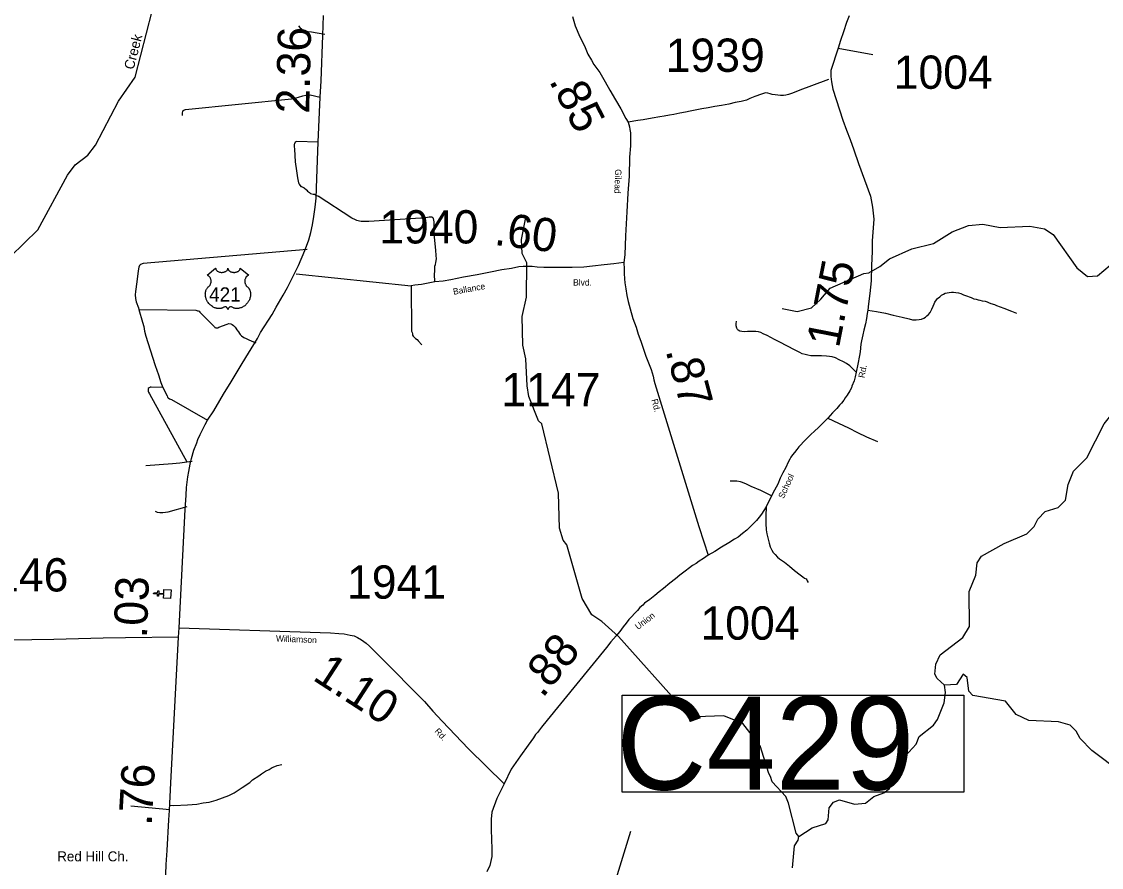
# Model space of a CAD drawing. Extents: x 2093524 to 2270757, y 289120 to 570408.
# Drawn here: x 2218962 to 2235181, y 409015 to 421724 of the extents above; entities that cross this region are included whole.
import ezdxf

# ---------------------------------------------------------------- set-up
doc = ezdxf.new("R2010")
doc.units = 0
for name, color, linetype in [('Exist Cultural Church CELL', 7, 'Continuous'), ('Exist Cultural Church with Cemetery Label', 7, 'Continuous'), ('Exist Hydrographic Creek Single Shore', 7, 'Continuous'), ('Exist Hydrographic Creek Single Shore Label', 7, 'Continuous'), ('Exist Hydrographic Misc Water Feature', 7, 'Continuous'), ('Exist Road Non-System Type 51', 7, 'Continuous'), ('Exist Road Primary US Attributed', 7, 'Continuous'), ('Exist Road Primary US Mileage Hundredths English Label', 7, 'Continuous'), ('Exist Road Primary US Shield CELL', 7, 'Continuous'), ('Exist Road Primary US Shield Number Label', 7, 'Continuous'), ('Exist Road Secondary Mileage Hundredths English Label', 7, 'Continuous'), ('Exist Road Secondary Structure Culvert Number Label', 7, 'Continuous'), ('Exist Road Secondary Type 20 Attributed', 7, 'Continuous'), ('Exist Road Secondary Type 51 Attributed', 7, 'Continuous'), ('Exist Road Secondary Type 51 Label', 7, 'Continuous'), ('Exist Road Secondary Type 51 Number Label', 7, 'Continuous')]:
    doc.layers.add(name, color=color, linetype=linetype)

msp = doc.modelspace()

# ---------------------------------------------------------------- linework, layer by layer
at = {"layer": 'Exist Cultural Church CELL'}
msp.add_lwpolyline([(2221094, 413061), (2221097, 413117), (2221021, 413122), (2221019, 413090), (2221003, 413091), (2221005, 413123), (2220945, 413126), (2220946, 413142), (2221006, 413139), (2221008, 413171), (2221024, 413170), (2221022, 413138), (2221098, 413133), (2221101, 413191), (2221208, 413185), (2221200, 413054)], close=True, dxfattribs=at)
at = {"layer": 'Exist Hydrographic Creek Single Shore'}
for points in [[(2218324, 417489), (2218794, 418192), (2219207, 418594), (2219652, 419415), (2219767, 419573), (2219958, 419717), (2220073, 419865), (2220418, 420528), (2220666, 420887), (2220925, 421879), (2221162, 422556), (2221161, 422822), (2221126, 422954), (2220899, 423319), (2220868, 423568), (2220830, 423656)], [(2232823, 411753), (2232714, 411853), (2232680, 411920), (2232695, 412067), (2232761, 412210), (2233100, 412472), (2233199, 412637), (2233194, 413162), (2233293, 413406), (2233316, 413589), (2233382, 413690), (2233722, 413883), (2234062, 414027), (2234170, 414137), (2234227, 414247), (2234334, 414363), (2234534, 414425), (2234641, 414534), (2234681, 414766), (2234763, 414968), (2234961, 415167), (2235223, 415680), (2235363, 415854), (2235430, 415856)], [(2235483, 410434), (2235038, 410771), (2234862, 410954), (2234803, 411061), (2234710, 411151), (2234535, 411200), (2234093, 411222), (2233901, 411311), (2233741, 411511), (2233249, 411597), (2233190, 411663), (2233163, 411871), (2233105, 411921), (2233006, 411762), (2232823, 411753)], [(2232093, 410396), (2232232, 410689), (2232397, 410866), (2232446, 410983), (2232661, 411152), (2232719, 411237), (2232817, 411487), (2232841, 411644), (2232823, 411753)], [(2230636, 409481), (2230835, 409608), (2231043, 409676), (2231076, 409728), (2231091, 409911), (2231157, 409995), (2231248, 410029), (2231473, 409963), (2231640, 409982), (2231764, 410081), (2231914, 410134), (2231996, 410201), (2232093, 410396)], [(2230540, 409007), (2230571, 409341), (2230628, 409422), (2230636, 409481)]]:
    msp.add_lwpolyline(points, dxfattribs=at)
at = {"layer": 'Exist Hydrographic Misc Water Feature'}
for points in [[(2230210, 410381), (2230185, 410424), (2230057, 410840), (2229796, 411177), (2229512, 411294), (2229095, 411279), (2228894, 411405), (2227928, 412486), (2227676, 412711), (2227525, 412809), (2227382, 413058), (2227150, 413863), (2227099, 413930), (2227040, 414111), (2227027, 414636), (2226777, 415678), (2226727, 415725), (2226582, 416092), (2226556, 416250), (2226536, 416657), (2226492, 416864), (2226481, 417291), (2226545, 417581), (2226549, 418100), (2226481, 418239), (2226471, 418449), (2226535, 418782)], [(2230386, 417413), (2230611, 417366), (2230827, 417424), (2230968, 417552), (2231108, 417720), (2231615, 417940), (2231689, 417948), (2231855, 418043), (2231996, 418158), (2232336, 418312), (2232660, 418391), (2232942, 418566), (2233183, 418660), (2233399, 418678), (2233658, 418630), (2234108, 418651), (2234324, 418611), (2234459, 418523), (2234812, 418024), (2234972, 417893), (2235122, 417903), (2235312, 418063)], [(2230636, 409481), (2230594, 409531), (2230482, 409979), (2230440, 410078), (2230238, 410302), (2230210, 410381)]]:
    msp.add_lwpolyline(points, dxfattribs=at)
at = {"layer": 'Exist Road Non-System Type 51'}
for p, q in [((2231225, 421326), (2231749, 421232)), ((2223084, 417932), (2224813, 417756)), ((2224871, 417762), (2224813, 417756)), ((2221444, 415108), (2221524, 415118)), ((2220603, 409938), (2221189, 409886))]:
    msp.add_line(p, q, dxfattribs=at)
for points in [[(2223120, 421662), (2223140, 421636), (2223169, 421609), (2223199, 421589), (2223229, 421583), (2223265, 421575), (2223315, 421570), (2223519, 421537)], [(2231083, 420855), (2230826, 420759), (2230652, 420692), (2230541, 420647), (2230481, 420628), (2230439, 420620), (2230405, 420614), (2230359, 420615), (2230319, 420617), (2230281, 420623), (2230235, 420630), (2230205, 420638), (2230173, 420648), (2230143, 420653), (2230121, 420651), (2230075, 420635), (2229975, 420596), (2229902, 420566), (2229850, 420543), (2229812, 420533), (2229772, 420523), (2229682, 420506), (2229583, 420485), (2229475, 420464), (2229377, 420447), (2229273, 420426), (2229177, 420412), (2229078, 420393), (2229006, 420378), (2228932, 420363), (2228848, 420347), (2228758, 420330), (2228694, 420316), (2228614, 420305), (2228550, 420292), (2228431, 420273), (2228299, 420250), (2228219, 420236), (2228071, 420213)], [(2221380, 420315), (2221380, 420341), (2221384, 420385), (2221398, 420393), (2221410, 420397), (2221424, 420403), (2223016, 420564), (2223120, 420589), (2223186, 420609), (2223232, 420617), (2223295, 420624), (2223445, 420590)], [(2223416, 419912), (2223090, 419921), (2223070, 419913), (2223059, 419889), (2223057, 419879), (2223057, 419863), (2223057, 419847), (2223059, 419805), (2223073, 419619), (2223090, 419481), (2223104, 419377), (2223121, 419303), (2223131, 419281), (2223139, 419267), (2223145, 419260), (2223155, 419248), (2223165, 419244), (2223195, 419232), (2223207, 419226), (2223241, 419196), (2223249, 419190), (2223259, 419176), (2223285, 419155), (2223304, 419143), (2223322, 419137), (2223344, 419131), (2223362, 419129), (2223374, 419121), (2223416, 419101)], [(2225170, 417812), (2225165, 417928), (2225169, 417974), (2225170, 418050), (2225180, 418076), (2225184, 418102), (2225196, 418158), (2225189, 418208), (2225184, 418290), (2225173, 418384), (2225165, 418492), (2225160, 418607), (2225157, 418675), (2225157, 418717), (2225155, 418739), (2225147, 418764), (2225138, 418776), (2225124, 418785), (2225086, 418783), (2225011, 418772), (2224960, 418770), (2224176, 418721), (2224090, 418718), (2224064, 418720), (2224038, 418724), (2223996, 418736), (2223976, 418746), (2223922, 418771), (2223416, 419101)], [(2223252, 418299), (2220786, 418090), (2220746, 418076), (2220734, 418061), (2220724, 418035), (2220713, 417979), (2220694, 417815), (2220673, 417669), (2220667, 417619), (2220674, 417563), (2220684, 417515), (2220717, 417421), (2220723, 417398)], [(2224813, 417756), (2224821, 417074), (2224829, 417050), (2224832, 417030), (2224836, 417012), (2224844, 416998), (2224854, 416986), (2224880, 416961), (2224904, 416947), (2224918, 416925), (2224975, 416869)], [(2231673, 417387), (2231801, 417370), (2231937, 417345), (2232051, 417314), (2232190, 417282), (2232296, 417256), (2232346, 417245), (2232400, 417243), (2232442, 417248), (2232478, 417254), (2232513, 417270), (2232537, 417282), (2232561, 417303), (2232585, 417321), (2232609, 417355), (2232620, 417375), (2232636, 417405), (2232652, 417449), (2232668, 417481), (2232681, 417509), (2232703, 417542), (2232719, 417562), (2232753, 417590), (2232781, 417612), (2232807, 417629), (2232836, 417641), (2232894, 417655), (2232928, 417657), (2232960, 417656), (2232994, 417654), (2233034, 417646), (2233068, 417638), (2233108, 417619), (2233168, 417599), (2233196, 417590), (2233227, 417576), (2233265, 417560), (2233299, 417551), (2233331, 417541), (2233357, 417537), (2233389, 417527), (2233433, 417522), (2233465, 417512), (2233485, 417502), (2233519, 417490), (2233577, 417471), (2233605, 417459), (2233718, 417418), (2233830, 417375), (2233906, 417344)], [(2220723, 417398), (2220778, 417208), (2220797, 417142), (2220809, 417074), (2220826, 416995), (2220895, 416791), (2220969, 416556), (2221018, 416418), (2221056, 416302), (2221085, 416225)], [(2220723, 417398), (2221581, 417386), (2221592, 417384), (2221605, 417380), (2221613, 417378), (2221631, 417372), (2221641, 417358), (2221858, 417140), (2221866, 417130), (2221872, 417126), (2221880, 417124), (2221894, 417122), (2221908, 417124), (2221924, 417132), (2222050, 417177), (2222076, 417187), (2222104, 417183), (2222126, 417171), (2222144, 417157), (2222168, 417134), (2222180, 417118), (2222196, 417090), (2222220, 417062), (2222235, 417038), (2222247, 417020), (2222267, 417001), (2222299, 416979), (2222335, 416961), (2222377, 416943), (2222481, 416898)], [(2231500, 416458), (2231448, 416506), (2231404, 416552), (2231350, 416589), (2231305, 416613), (2231243, 416644), (2231185, 416670), (2231139, 416685), (2231095, 416691), (2231051, 416699), (2230979, 416702), (2230923, 416702), (2230859, 416701), (2230815, 416703), (2230773, 416712), (2230731, 416722), (2230685, 416733), (2230649, 416751), (2230590, 416781), (2230540, 416806), (2230494, 416832), (2230436, 416861), (2230373, 416897), (2230273, 416946), (2230159, 417009), (2230102, 417033), (2230068, 417054), (2230030, 417060), (2229990, 417066), (2229922, 417065), (2229864, 417067), (2229822, 417064), (2229782, 417068), (2229752, 417070), (2229726, 417087), (2229714, 417099), (2229706, 417119), (2229694, 417153), (2229696, 417185), (2229699, 417221)], [(2221085, 416225), (2220909, 416232), (2220895, 416229), (2220887, 416227), (2220877, 416221), (2220865, 416213), (2220863, 416209), (2220861, 416199), (2220863, 416183), (2220863, 416173), (2220869, 416157), (2220882, 416131), (2221444, 415108)], [(2221085, 416225), (2221148, 416103), (2221156, 416083), (2221166, 416073), (2221184, 416058), (2221216, 416044), (2221756, 415733)], [(2231072, 415767), (2231233, 415690), (2231381, 415618), (2231520, 415551), (2231652, 415486), (2231817, 415413)], [(2220827, 415055), (2221231, 415086), (2221339, 415095), (2221444, 415108)], [(2230228, 414597), (2230068, 414677), (2229921, 414740), (2229849, 414776), (2229791, 414801), (2229759, 414811), (2229703, 414819), (2229651, 414820), (2229607, 414818)], [(2220968, 414369), (2220998, 414355), (2221038, 414349), (2221062, 414347), (2221086, 414347), (2221124, 414352), (2221166, 414358), (2221451, 414438)], [(2230148, 414434), (2230143, 414300), (2230140, 414184), (2230148, 414088), (2230157, 414025), (2230174, 413947), (2230190, 413889), (2230207, 413833), (2230233, 413781), (2230253, 413749), (2230281, 413718), (2230318, 413678), (2230348, 413654), (2230420, 413599), (2230495, 413539), (2230571, 413478), (2230656, 413411), (2230696, 413383), (2230724, 413363), (2230746, 413350), (2230756, 413334), (2230763, 413320), (2230775, 413296)], [(2221194, 409950), (2221250, 409947), (2221454, 409956), (2221596, 409965), (2221688, 409983), (2221780, 409996), (2221887, 410025), (2222073, 410098), (2222154, 410137), (2222274, 410214), (2222389, 410292), (2222429, 410329), (2222526, 410393), (2222568, 410420), (2222628, 410460), (2222682, 410488), (2222724, 410515), (2222764, 410529), (2222799, 410545), (2222869, 410563)]]:
    msp.add_lwpolyline(points, dxfattribs=at)
at = {"layer": 'Exist Road Primary US Attributed'}
msp.add_line((2221320, 412475), (2221330, 412617), dxfattribs=at)
for points in [[(2221330, 412617), (2221418, 414395), (2221432, 414607), (2221441, 414725), (2221458, 414885), (2221472, 414965), (2221492, 415073), (2221513, 415161), (2221549, 415285), (2221593, 415395), (2221610, 415446), (2221643, 415522), (2221683, 415600), (2221720, 415671), (2221756, 415733), (2221849, 415877), (2221938, 416033), (2221995, 416124), (2222112, 416310), (2222276, 416588), (2222505, 416963), (2222552, 417052), (2222724, 417322), (2222785, 417432), (2222893, 417612), (2222958, 417731), (2223057, 417927), (2223120, 418060), (2223217, 418282), (2223241, 418348), (2223279, 418447), (2223308, 418554), (2223333, 418668), (2223354, 418793), (2223373, 418934), (2223385, 419073), (2223396, 419367), (2223416, 419912), (2223445, 420590), (2223463, 420835), (2223487, 421514), (2223498, 421817)], [(2221109, 408428), (2221121, 408700), (2221124, 408770), (2221136, 409058), (2221151, 409270), (2221176, 409728), (2221184, 409871), (2221203, 410287), (2221320, 412475)]]:
    msp.add_lwpolyline(points, dxfattribs=at)
at = {"layer": 'Exist Road Primary US Shield CELL'}
msp.add_lwpolyline([(2221877, 418017), (2221878, 418012), (2221879, 418006), (2221880, 418002), (2221883, 417996), (2221888, 417989), (2221895, 417982), (2221902, 417975), (2221907, 417972), (2221916, 417967), (2221926, 417963), (2221937, 417960), (2221949, 417958), (2221961, 417956), (2221973, 417956), (2221986, 417957), (2222001, 417960), (2222008, 417962), (2222015, 417964), (2222022, 417967), (2222030, 417971), (2222036, 417975), (2222041, 417979), (2222048, 417985), (2222053, 417992), (2222055, 417996), (2222057, 417999), (2222060, 418007), (2222061, 418010), (2222061, 418018), (2222062, 418012), (2222062, 418008), (2222063, 418004), (2222065, 418000), (2222068, 417995), (2222071, 417990), (2222077, 417984), (2222080, 417980), (2222083, 417978), (2222092, 417972), (2222102, 417966), (2222107, 417964), (2222112, 417962), (2222119, 417960), (2222126, 417959), (2222132, 417958), (2222139, 417957), (2222146, 417956), (2222152, 417956), (2222159, 417956), (2222165, 417956), (2222172, 417957), (2222179, 417958), (2222185, 417960), (2222193, 417962), (2222200, 417964), (2222206, 417967), (2222214, 417971), (2222220, 417975), (2222225, 417979), (2222231, 417984), (2222236, 417990), (2222239, 417995), (2222241, 417999), (2222243, 418004), (2222245, 418009), (2222245, 418014), (2222245, 418018), (2222374, 417915), (2222371, 417914), (2222364, 417911), (2222359, 417907), (2222350, 417901), (2222346, 417898), (2222342, 417894), (2222339, 417890), (2222335, 417887), (2222332, 417882), (2222328, 417876), (2222325, 417871), (2222323, 417866), (2222319, 417856), (2222317, 417849), (2222316, 417843), (2222314, 417832), (2222314, 417826), (2222314, 417821), (2222314, 417815), (2222315, 417810), (2222316, 417804), (2222317, 417799), (2222318, 417793), (2222320, 417786), (2222323, 417779), (2222329, 417768), (2222337, 417756), (2222342, 417750), (2222347, 417745), (2222355, 417738), (2222360, 417734), (2222365, 417729), (2222373, 417720), (2222376, 417715), (2222379, 417710), (2222382, 417705), (2222385, 417700), (2222388, 417695), (2222392, 417684), (2222395, 417673), (2222397, 417668), (2222399, 417655), (2222400, 417649), (2222401, 417637), (2222401, 417622), (2222400, 417608), (2222398, 417591), (2222395, 417581), (2222392, 417570), (2222389, 417560), (2222383, 417545), (2222378, 417534), (2222371, 417522), (2222366, 417514), (2222361, 417506), (2222354, 417497), (2222346, 417487), (2222337, 417477), (2222329, 417469), (2222319, 417460), (2222313, 417455), (2222304, 417449), (2222292, 417441), (2222281, 417434), (2222271, 417429), (2222262, 417425), (2222251, 417421), (2222232, 417416), (2222225, 417414), (2222216, 417413), (2222209, 417412), (2222201, 417412), (2222191, 417412), (2222181, 417412), (2222172, 417414), (2222162, 417416), (2222152, 417419), (2222143, 417423), (2222133, 417427), (2222117, 417437), (2222113, 417440), (2222110, 417440), (2222104, 417441), (2222098, 417439), (2222092, 417437), (2222089, 417435), (2222084, 417432), (2222080, 417429), (2222076, 417425), (2222073, 417421), (2222071, 417419), (2222066, 417412), (2222064, 417408), (2222063, 417404), (2222061, 417398), (2222059, 417406), (2222057, 417411), (2222054, 417416), (2222051, 417420), (2222047, 417425), (2222043, 417429), (2222038, 417433), (2222033, 417436), (2222029, 417438), (2222025, 417439), (2222020, 417440), (2222016, 417441), (2222013, 417441), (2222009, 417440), (2222003, 417435), (2221998, 417432), (2221992, 417428), (2221985, 417424), (2221979, 417422), (2221973, 417419), (2221966, 417417), (2221958, 417415), (2221950, 417413), (2221943, 417412), (2221935, 417411), (2221928, 417411), (2221921, 417411), (2221914, 417412), (2221906, 417412), (2221897, 417414), (2221889, 417416), (2221880, 417418), (2221871, 417421), (2221862, 417424), (2221850, 417429), (2221842, 417434), (2221829, 417441), (2221814, 417451), (2221803, 417461), (2221795, 417468), (2221782, 417481), (2221775, 417489), (2221764, 417503), (2221757, 417514), (2221752, 417522), (2221745, 417534), (2221741, 417542), (2221737, 417553), (2221733, 417564), (2221730, 417574), (2221728, 417580), (2221725, 417591), (2221724, 417599), (2221722, 417609), (2221722, 417621), (2221721, 417631), (2221722, 417640), (2221723, 417650), (2221724, 417661), (2221727, 417670), (2221728, 417676), (2221731, 417684), (2221735, 417693), (2221739, 417702), (2221743, 417709), (2221748, 417717), (2221753, 417723), (2221760, 417730), (2221767, 417737), (2221773, 417742), (2221780, 417749), (2221784, 417753), (2221789, 417760), (2221793, 417765), (2221795, 417770), (2221799, 417778), (2221802, 417784), (2221805, 417792), (2221806, 417798), (2221808, 417806), (2221809, 417813), (2221809, 417823), (2221809, 417830), (2221808, 417839), (2221806, 417848), (2221804, 417855), (2221801, 417864), (2221798, 417870), (2221793, 417878), (2221788, 417886), (2221782, 417893), (2221776, 417898), (2221771, 417902), (2221766, 417906), (2221759, 417910), (2221753, 417913), (2221749, 417915)], close=True, dxfattribs=at)
at = {"layer": 'Exist Road Secondary Structure Culvert Number Label'}
msp.add_line((2226515, 404361), (2228111, 409560), dxfattribs=at)
msp.add_lwpolyline([(2227985, 411604), (2233117, 411604), (2233117, 410144), (2227985, 410144)], close=True, dxfattribs=at)
at = {"layer": 'Exist Road Secondary Type 20 Attributed'}
msp.add_lwpolyline([(2228009, 418105), (2227857, 418084), (2227711, 418069), (2227539, 418049), (2227405, 418036), (2227233, 418031), (2227060, 418027), (2226874, 418028), (2226806, 418027), (2226706, 418035), (2226632, 418044), (2226568, 418045), (2226498, 418045), (2226430, 418038), (2226320, 418015), (2226174, 417992), (2226007, 417961), (2225807, 417921), (2225601, 417884), (2225410, 417846), (2225292, 417825), (2225170, 417812), (2224969, 417772), (2224871, 417762)], dxfattribs=at)
at = {"layer": 'Exist Road Secondary Type 51 Attributed'}
for points in [[(2227236, 421799), (2227278, 421659), (2227349, 421495), (2227415, 421361), (2227468, 421235), (2227524, 421144), (2227555, 421078), (2227646, 420957), (2227728, 420819), (2227799, 420694), (2227883, 420549), (2227964, 420412), (2228037, 420270), (2228071, 420213), (2228094, 420145), (2228100, 420101), (2228109, 420051), (2228109, 420023), (2228110, 419961), (2228106, 419859), (2228094, 419685), (2228086, 419403), (2228070, 419145), (2228054, 418865), (2228033, 418507), (2228022, 418217), (2228009, 418105)], [(2231393, 421809), (2231352, 421709), (2231305, 421568), (2231262, 421442), (2231225, 421326), (2231119, 420990), (2231119, 420900), (2231126, 420817), (2231146, 420709), (2231298, 420245), (2231353, 420094), (2231408, 419950), (2231461, 419797), (2231531, 419593), (2231715, 419100), (2231743, 418937), (2231764, 418753), (2231738, 418428), (2231736, 418271), (2231727, 418059), (2231723, 417830), (2231701, 417638), (2231684, 417481), (2231673, 417387), (2231665, 417337), (2231652, 417261), (2231637, 417185), (2231611, 417087), (2231596, 417017), (2231579, 416929), (2231569, 416875), (2231558, 416761), (2231548, 416709), (2231525, 416579), (2231500, 416458), (2231483, 416386), (2231470, 416326), (2231434, 416244), (2231425, 416220), (2231403, 416176), (2231363, 416112), (2231332, 416069), (2231312, 416037), (2231278, 415993), (2231249, 415963), (2231207, 415912), (2231144, 415846), (2231072, 415767), (2231035, 415731), (2230987, 415682), (2230933, 415626), (2230874, 415568), (2230815, 415521), (2230767, 415471), (2230716, 415418), (2230658, 415356), (2230634, 415332), (2230604, 415296), (2230569, 415251), (2230543, 415213), (2230518, 415177), (2230500, 415147), (2230476, 415103), (2230441, 415024), (2230397, 414942), (2230358, 414862), (2230319, 414772), (2230272, 414683), (2230228, 414597), (2230148, 414434), (2230075, 414322), (2230043, 414277), (2229999, 414227), (2229950, 414175), (2229902, 414128), (2229853, 414082), (2229789, 414031), (2229725, 413977), (2229672, 413946), (2229586, 413894), (2229477, 413829), (2229376, 413764), (2229276, 413709)], [(2228009, 418105), (2228013, 418003), (2228012, 417939), (2228017, 417859), (2228021, 417797), (2228038, 417708), (2228055, 417608), (2228075, 417516), (2228104, 417406), (2228145, 417265), (2228192, 417135), (2228223, 417027), (2228264, 416920), (2228301, 416800), (2228340, 416699), (2228377, 416599), (2228417, 416497), (2228446, 416397), (2228461, 416342), (2228475, 416288), (2229135, 414136), (2229210, 413905), (2229276, 413709)], [(2229276, 413709), (2229205, 413659), (2229139, 413618), (2229095, 413582), (2229041, 413550), (2228996, 413517), (2228930, 413465), (2228851, 413408), (2228785, 413352), (2228698, 413285), (2228603, 413208), (2228541, 413155), (2228473, 413099), (2228396, 413041), (2228320, 412984), (2228292, 412956), (2228249, 412919), (2228211, 412877), (2228166, 412831), (2228126, 412787), (2228081, 412738), (2228041, 412686), (2227999, 412629), (2227948, 412561), (2227891, 412495), (2227815, 412406), (2227746, 412320), (2226854, 411225), (2226770, 411124), (2226709, 411042), (2226683, 411013), (2226652, 410963), (2226571, 410851), (2226454, 410694), (2226316, 410491), (2226211, 410273)], [(2221330, 412617), (2223447, 412543), (2223601, 412538), (2223727, 412530), (2223809, 412523), (2223895, 412506), (2223955, 412494), (2224010, 412471), (2224068, 412433), (2224136, 412384), (2224190, 412338), (2224353, 412175), (2225016, 411506), (2225139, 411361), (2225278, 411210), (2225675, 410795), (2226211, 410273)], [(2221320, 412475), (2220523, 412466), (2220187, 412458), (2219448, 412439), (2219114, 412433), (2218764, 412430)], [(2226211, 410273), (2226102, 410048), (2226025, 409847), (2226015, 409739), (2226015, 409597), (2226019, 409423), (2226025, 409302), (2226025, 409180), (2225994, 409042), (2225949, 408948)]]:
    msp.add_lwpolyline(points, dxfattribs=at)

# ---------------------------------------------------------------- texts
at = {"layer": 'Exist Cultural Church with Cemetery Label'}
msp.add_text('Red Hill Ch.', height=150, dxfattribs=at).set_placement((2219498, 409106))
at = {"layer": 'Exist Hydrographic Creek Single Shore Label'}
msp.add_text('Creek', height=150, rotation=75.3679, dxfattribs=at).set_placement((2220643, 420993))
at = {"layer": 'Exist Road Primary US Mileage Hundredths English Label'}
for s, rotation, p in [('2.36', 88.6204, (2223281, 420338)), ('.03', 88.1179, (2220845, 412454)), ('.76', 86.7401, (2220915, 409635))]:
    msp.add_text(s, height=500, rotation=rotation, dxfattribs=at).set_placement(p)
at = {"layer": 'Exist Road Primary US Shield Number Label'}
msp.add_text('421', height=212.5, dxfattribs=at).set_placement((2221779, 417518))
at = {"layer": 'Exist Road Secondary Mileage Hundredths English Label'}
for s, rotation, p in [('.85', 297.4313, (2226877, 420836)), ('.60', 352.7977, (2226049, 418370)), ('1.75', 78.9465, (2231238, 416808)), ('.87', 284.946, (2228633, 416782)), ('.88', 50.8082, (2226786, 411547)), ('1.10', 327.055, (2223316, 411843))]:
    msp.add_text(s, height=500, rotation=rotation, dxfattribs=at).set_placement(p)
at = {"layer": 'Exist Road Secondary Structure Culvert Number Label'}
msp.add_text('C429', height=1400, dxfattribs=at).set_placement((2227896, 410183))
at = {"layer": 'Exist Road Secondary Type 51 Label'}
for s, rotation, p in [('Gilead', 267.8261, (2227879, 419508)), ('Blvd.', 359.8714, (2227246, 417758)), ('Ballance', 10.3455, (2225452, 417618)), ('Rd.', 78.9465, (2231622, 416363)), ('Rd.', 284.4916, (2228422, 416041)), ('School', 65.7195, (2230410, 414548)), ('Union', 37.0049, (2228220, 412581)), ('Williamson', 357.5626, (2222781, 412410)), ('Rd.', 312.7594, (2225158, 411055))]:
    msp.add_text(s, height=95, rotation=rotation, dxfattribs=at).set_placement(p)
at = {"layer": 'Exist Road Secondary Type 51 Number Label'}
for s, p in [('1939', (2228637, 420969)), ('1004', (2232062, 420714)), ('1940', (2224335, 418390)), ('1147', (2226169, 415943)), ('1146', (2218177, 413161)), ('1941', (2223850, 413053)), ('1004', (2229159, 412437))]:
    msp.add_text(s, height=500, dxfattribs=at).set_placement(p)

doc.saveas('drawing.dxf')
